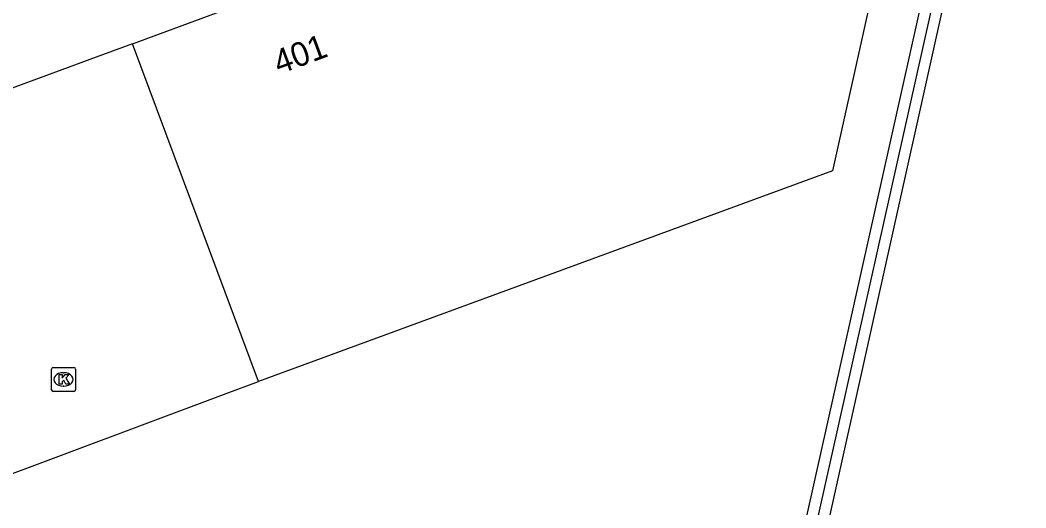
# Model space of a CAD drawing. Extents: x 161389 to 162585, y 388479 to 389761.
# Drawn here: x 162080.24 to 162122.01, y 388775.65 to 388795.9 of the extents above; entities that cross this region are included whole.
import ezdxf

# ---------------------------------------------------------------- set-up
doc = ezdxf.new("R2010")
doc.units = 0
for name, color, linetype in [('IMGEO_Groenvoorziening', 7, 'Continuous'), ('IMGEO_Kolk', 7, 'Continuous'), ('IMGEO_Muur', 7, 'Continuous'), ('IMGEO_Pand', 7, 'Continuous'), ('IMGEO_Pand_nummerreeks', 7, 'Continuous'), ('IMGEO_Pand_overbouw', 7, 'Continuous')]:
    doc.layers.add(name, color=color, linetype=linetype)

msp = doc.modelspace()

# ---------------------------------------------------------------- linework, layer by layer
at = {"layer": 'IMGEO_Groenvoorziening'}
msp.add_lwpolyline([(162122.012, 388811.944), (162107.264, 388745.692)], dxfattribs=at)
at = {"layer": 'IMGEO_Kolk'}
for p, q in [((162081.546, 388780.553), (162081.546, 388781.405)), ((162081.621, 388781.479), (162082.473, 388781.479)), ((162082.034, 388781.259), (162082.059, 388781.259)), ((162082.547, 388781.405), (162082.547, 388780.553)), ((162082.473, 388780.479), (162081.621, 388780.479)), ((162082.057, 388780.699), (162082.032, 388780.699))]:
    msp.add_line(p, q, dxfattribs=at)
for points in [[(162081.546, 388780.553), (162081.546, 388781.405)], [(162081.621, 388781.479), (162082.473, 388781.479)], [(162081.867, 388781.179), (162081.99, 388781.179), (162081.99, 388781.028), (162082.12, 388781.179), (162082.284, 388781.179), (162082.138, 388781.028), (162082.291, 388780.779), (162082.139, 388780.779), (162082.054, 388780.943), (162081.99, 388780.876), (162081.99, 388780.779), (162081.867, 388780.779), (162081.867, 388781.179)], [(162082.547, 388781.405), (162082.547, 388780.553)], [(162082.473, 388780.479), (162081.621, 388780.479)]]:
    msp.add_lwpolyline(points, dxfattribs=at)
for centre, start, end in [((162081.623, 388781.403), 91.552, 178.448), ((162081.623, 388781.403), 91.552, 178.448), ((162082.471, 388781.403), 1.552, 88.448), ((162082.471, 388781.403), 1.552, 88.448), ((162081.623, 388780.555), 181.552, 268.448), ((162081.623, 388780.555), 181.552, 268.448), ((162082.471, 388780.555), 271.552, 358.448), ((162082.471, 388780.555), 271.552, 358.448)]:
    msp.add_arc(centre, 0.0765, start, end, dxfattribs=at)
for centre, major_axis, ratio, start_param, end_param in [((162082.033, 388780.979), (-0.387, 0.002), 0.722429, 4.712389, 7.853982), ((162082.058, 388780.979), (-0.39, 0.002), 0.717154, 1.570796, 4.712389)]:
    msp.add_ellipse(centre, major_axis=major_axis, ratio=ratio, start_param=start_param, end_param=end_param, dxfattribs=at)
at = {"layer": 'IMGEO_Muur'}
for points in [[(162090.089, 388796.832), (162089.771, 388797.682), (162120.964, 388809.223), (162106.946, 388746.548), (162107.264, 388745.692)], [(162105.908, 388749.278), (162106.664, 388747.307), (162120.333, 388808.51), (162090.394, 388797.404), (162090.544, 388797)]]:
    msp.add_lwpolyline(points, dxfattribs=at)
at = {"layer": 'IMGEO_Pand'}
msp.add_lwpolyline([(162090.544, 388797), (162117.872, 388807.131), (162113.978, 388789.645), (162090.149, 388780.9), (162084.904, 388794.91), (162090.089, 388796.832)], dxfattribs=at)
at = {"layer": 'IMGEO_Pand_overbouw'}
msp.add_lwpolyline([(162084.904, 388794.91), (162083.664, 388794.453), (162073.411, 388790.673), (162072.666, 388790.398), (162077.866, 388776.304), (162078.586, 388776.573), (162088.806, 388780.397), (162090.149, 388780.9)], close=True, dxfattribs=at)

# ---------------------------------------------------------------- texts
at = {"layer": 'IMGEO_Pand_nummerreeks'}
msp.add_text('401', height=1, rotation=20.2976, dxfattribs=at).set_placement((162090.994, 388793.633))

doc.saveas('drawing.dxf')
